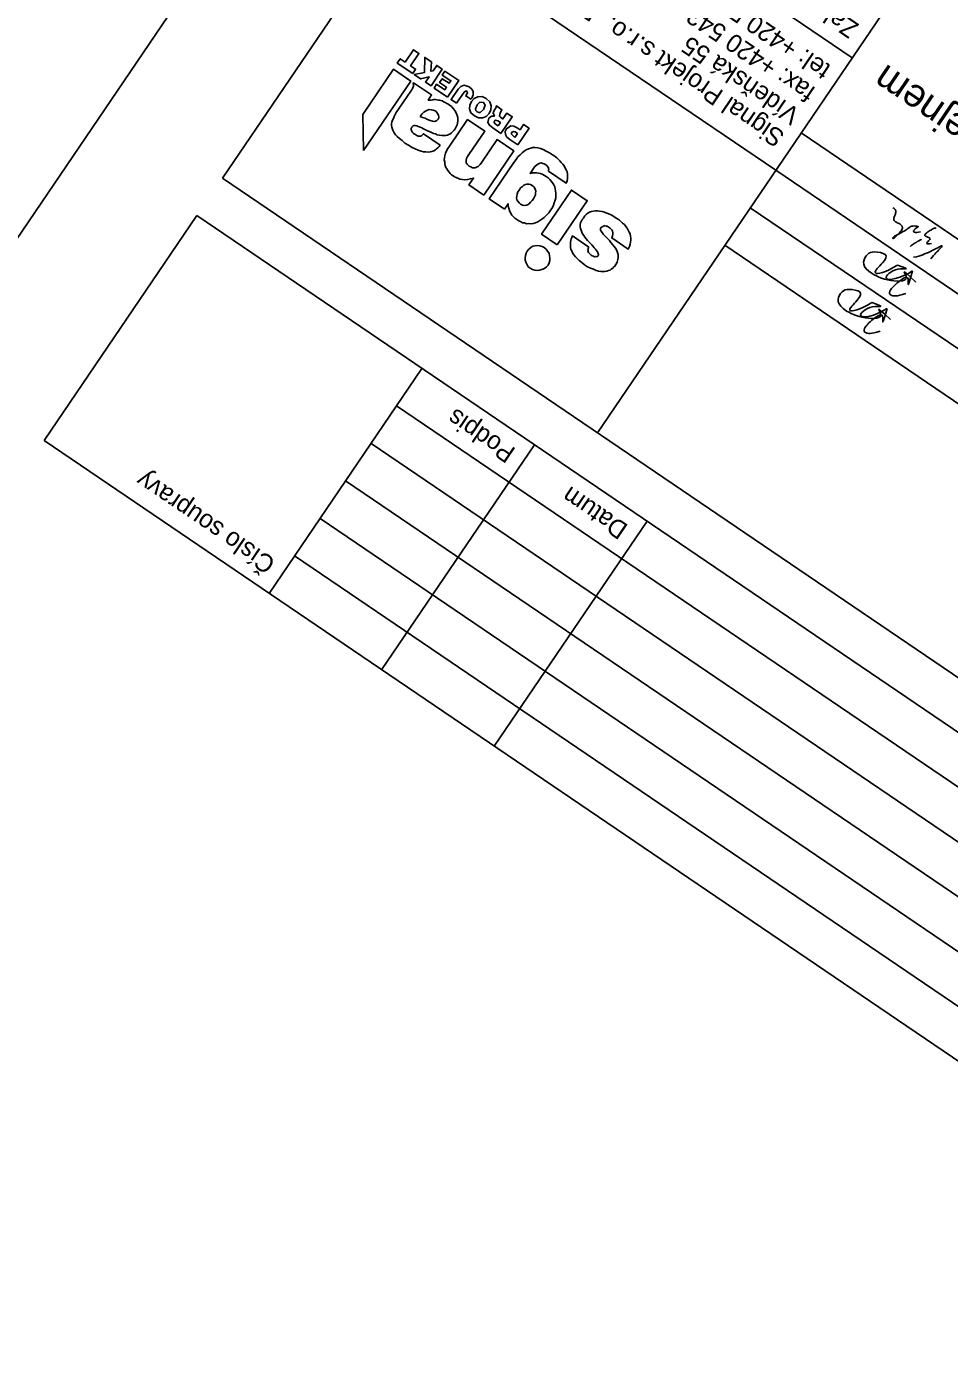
# Model space of a CAD drawing. Extents: x -621145 to -620110, y -1122807 to -1121971.
# Drawn here: x -621094.2 to -621043.4, y -1122204.9 to -1122131.1 of the extents above; entities that cross this region are included whole.
import ezdxf

# ---------------------------------------------------------------- set-up
doc = ezdxf.new("R2010")
doc.units = 0
for name, color, linetype in [('Default', 7, 'Continuous'), ('Info o rozpiskách', 7, 'Continuous'), ('LICHE', 7, 'Continuous'), ('Podpisy', 7, 'Continuous'), ('popis', 7, 'Continuous'), ('Ramečky', 7, 'Continuous'), ('RÁMY', 7, 'Continuous'), ('Text', 7, 'Continuous'), ('Text barevný', 7, 'Continuous')]:
    doc.layers.add(name, color=color, linetype=linetype)

# ---------------------------------------------------------------- blocks, each defined once
blk = doc.blocks.new('A$C65FD2E33_1')
at = {"layer": 'popis'}
for points in [[(-0.001696, 0.001402), (-0.001243, 0.00199), (-0.000783, 0.002198), (-0.00058, 0.001995), (-0.000655, 0.001241), (-0.001176, -0.000273), (-0.001696, 0.001402), (-0.001176, -0.000273)], [(0, 0), (0.000429, 0.000991), (0.001306, 0.001883), (0.000916, 0.000325), (0.00104, -0.00033), (0.00205, 0.000162), (0.002331, 0.000523), (0.002284, 0.001298), (0.001686, 0.001657), (0.000024, 0.001491), (-0.001834, 0.000276), (0, 0), (-0.001834, 0.000276)], [(-0.001176, -0.000273), (-0.00069, 0.000816), (0.000494, 0.001844), (0, 0), (-0.001176, -0.000273), (0, 0)]]:
    blk.add_open_spline(points, degree=3, dxfattribs=at)
blk = doc.blocks.new('podpis_vyvoda')
at = {"layer": 'Default'}
for points, degree in [([(0.027, 0.238), (0.019, 0.149), (-0.001, 0.052), (-0.009, -0.025), (0.03, 0.048), (0.089, 0.161), (0.154, 0.255), (0.197, 0.319), (0.239, 0.357)], 3), ([(0.289, 0.083), (0.328, 0.161), (0.348, 0.206), (0.366, 0.257)], 2), ([(0.361, 0.009), (0.395, 0.041), (0.415, 0.059), (0.44, 0.059), (0.446, 0.056), (0.449, 0.046), (0.448, 0.031), (0.447, 0.012), (0.439, -0.011), (0.429, -0.026), (0.425, -0.037), (0.431, -0.039), (0.466, -0.022), (0.498, 0), (0.518, 0.019), (0.527, 0.042), (0.531, 0.068), (0.542, 0.096), (0.556, 0.126), (0.582, 0.173), (0.6, 0.207), (0.62, 0.245), (0.63, 0.266), (0.634, 0.282), (0.636, 0.302), (0.629, 0.305), (0.62, 0.291), (0.614, 0.271), (0.61, 0.243), (0.596, 0.181), (0.594, 0.151), (0.596, 0.113), (0.605, 0.097), (0.62, 0.085), (0.645, 0.077), (0.675, 0.079), (0.701, 0.085), (0.734, 0.088), (0.757, 0.086), (0.775, 0.068), (0.783, 0.042), (0.788, 0.018), (0.795, -0.004), (0.804, -0.027), (0.816, -0.045), (0.832, -0.054), (0.848, -0.058), (0.874, -0.055)], 3), ([(0.141, 0.058), (0.176, 0.089), (0.196, 0.096), (0.203, 0.087), (0.195, 0.044), (0.19, 0.021), (0.197, 0.004), (0.217, 0.007), (0.27, 0.019), (0.283, 0.019), (0.288, 0.002), (0.28, -0.031), (0.269, -0.069), (0.243, -0.119), (0.227, -0.15), (0.219, -0.158), (0.203, -0.155)], 3)]:
    blk.add_open_spline(points, degree=degree, dxfattribs=at)

msp = doc.modelspace()

# ---------------------------------------------------------------- linework, layer by layer
at = {"layer": 'Info o rozpiskách'}
for points in [[(-621072.952, -1122133.722), (-621073.801, -1122133.146), (-621073.638, -1122132.906), (-621073.368, -1122133.09), (-621072.907, -1122132.411), (-621072.606, -1122132.615), (-621073.067, -1122133.294), (-621072.79, -1122133.483), (-621072.952, -1122133.722)], [(-621071.941, -1122134.409), (-621072.25, -1122134.199), (-621072.05, -1122133.906), (-621072.512, -1122134.021), (-621072.867, -1122133.78), (-621072.292, -1122133.663), (-621072.282, -1122132.835), (-621071.919, -1122133.082), (-621071.942, -1122133.596), (-621071.825, -1122133.574), (-621071.626, -1122133.281), (-621071.317, -1122133.49), (-621071.941, -1122134.409)], [(-621071.023, -1122135.033), (-621071.771, -1122134.524), (-621071.63, -1122134.316), (-621071.182, -1122134.62), (-621071.088, -1122134.481), (-621071.466, -1122134.224), (-621071.319, -1122134.008), (-621070.941, -1122134.265), (-621070.847, -1122134.126), (-621071.317, -1122133.806), (-621071.171, -1122133.59), (-621070.399, -1122134.114), (-621071.023, -1122135.033)], [(-621070.529, -1122135.368), (-621070.83, -1122135.164), (-621070.442, -1122134.592), (-621070.29, -1122134.436), (-621070.122, -1122134.37), (-621069.835, -1122134.463), (-621069.692, -1122134.583), (-621069.618, -1122134.724), (-621069.619, -1122134.892), (-621069.698, -1122135.075), (-621069.753, -1122135.139), (-621070.023, -1122134.956), (-621069.934, -1122134.791), (-621069.964, -1122134.703), (-621070.039, -1122134.697), (-621070.115, -1122134.758), (-621070.529, -1122135.368)], [(-621069.549, -1122136.067), (-621069.737, -1122135.894), (-621069.826, -1122135.676), (-621069.805, -1122135.464), (-621069.716, -1122135.266), (-621069.554, -1122135.094), (-621069.357, -1122135.003), (-621069.129, -1122134.999), (-621068.894, -1122135.102), (-621068.705, -1122135.288), (-621068.621, -1122135.513), (-621068.649, -1122135.72), (-621068.743, -1122135.926), (-621068.9, -1122136.091), (-621069.092, -1122136.174), (-621069.32, -1122136.177), (-621069.549, -1122136.067)], [(-621069.397, -1122135.843), (-621069.31, -1122135.88), (-621069.224, -1122135.871), (-621069.047, -1122135.709), (-621068.957, -1122135.477), (-621069.046, -1122135.326), (-621069.245, -1122135.304), (-621069.399, -1122135.447), (-621069.484, -1122135.672), (-621069.472, -1122135.77), (-621069.397, -1122135.843)], [(-621068.083, -1122137.029), (-621068.531, -1122136.725), (-621068.72, -1122136.573), (-621068.81, -1122136.423), (-621068.754, -1122136.19), (-621068.608, -1122136.075), (-621068.447, -1122136.071), (-621068.516, -1122135.889), (-621068.434, -1122135.719), (-621068.387, -1122135.65), (-621068.347, -1122135.575), (-621068.355, -1122135.536), (-621068.339, -1122135.513), (-621068.03, -1122135.723), (-621068.125, -1122135.896), (-621068.17, -1122136.079), (-621068.114, -1122136.129), (-621068.026, -1122136.199), (-621067.98, -1122136.23), (-621067.76, -1122135.906), (-621067.459, -1122136.111), (-621068.083, -1122137.029)], [(-621068.242, -1122136.616), (-621068.117, -1122136.431), (-621068.248, -1122136.342), (-621068.377, -1122136.299), (-621068.437, -1122136.338), (-621068.453, -1122136.428), (-621068.389, -1122136.517), (-621068.242, -1122136.616)], [(-621067.157, -1122137.658), (-621067.597, -1122137.359), (-621067.756, -1122137.228), (-621067.838, -1122137.083), (-621067.847, -1122136.93), (-621067.77, -1122136.768), (-621067.546, -1122136.604), (-621067.375, -1122136.619), (-621067.182, -1122136.716), (-621067.028, -1122136.821), (-621066.834, -1122136.535), (-621066.533, -1122136.74), (-621067.157, -1122137.658)], [(-621067.316, -1122137.245), (-621067.175, -1122137.037), (-621067.306, -1122136.948), (-621067.399, -1122136.918), (-621067.495, -1122136.977), (-621067.511, -1122137.068), (-621067.401, -1122137.188), (-621067.316, -1122137.245)], [(-621066.475, -1122144.458), (-621066.578, -1122144.377), (-621066.645, -1122144.276), (-621066.7, -1122144.159), (-621066.753, -1122144.021), (-621066.758, -1122143.894), (-621066.736, -1122143.762), (-621066.701, -1122143.628), (-621066.635, -1122143.515), (-621066.554, -1122143.412), (-621066.437, -1122143.323), (-621066.323, -1122143.254), (-621066.214, -1122143.226), (-621066.056, -1122143.209), (-621065.937, -1122143.234), (-621065.818, -1122143.258), (-621065.705, -1122143.324), (-621065.586, -1122143.415), (-621065.512, -1122143.522), (-621065.43, -1122143.634), (-621065.411, -1122143.771), (-621065.389, -1122143.888), (-621065.388, -1122144.035), (-621065.435, -1122144.172), (-621065.485, -1122144.296), (-621065.582, -1122144.388), (-621065.686, -1122144.475), (-621065.824, -1122144.528), (-621065.951, -1122144.566), (-621066.075, -1122144.583), (-621066.22, -1122144.564), (-621066.346, -1122144.534), (-621066.475, -1122144.458)]]:
    msp.add_lwpolyline(points, dxfattribs=at)
at = {"layer": 'popis'}
for points in [[(-621075.658, -1122137.973), (-621073.054, -1122134.138), (-621074.011, -1122133.488), (-621075.704, -1122135.981), (-621075.658, -1122137.973)], [(-621071.439, -1122137.671), (-621072.357, -1122137.047), (-621072.412, -1122137.111), (-621072.464, -1122137.154), (-621072.521, -1122137.172), (-621072.581, -1122137.177), (-621072.648, -1122137.176), (-621072.72, -1122137.15), (-621072.774, -1122137.113), (-621072.836, -1122137.071), (-621072.905, -1122137.024), (-621072.969, -1122136.969), (-621073.003, -1122136.902), (-621073.023, -1122136.865), (-621073.033, -1122136.813), (-621073.043, -1122136.761), (-621073.016, -1122136.723), (-621073.006, -1122136.674), (-621072.964, -1122136.646), (-621072.925, -1122136.605), (-621072.865, -1122136.6), (-621072.806, -1122136.596), (-621072.731, -1122136.601), (-621072.643, -1122136.638), (-621072.548, -1122136.68), (-621072.452, -1122136.723), (-621072.354, -1122136.778), (-621072.244, -1122136.83), (-621072.141, -1122136.878), (-621072.03, -1122136.931), (-621071.914, -1122136.975), (-621071.803, -1122137.028), (-621071.697, -1122137.055), (-621071.594, -1122137.103), (-621071.475, -1122137.127), (-621071.351, -1122137.144), (-621071.232, -1122137.134), (-621071.136, -1122137.143), (-621071.04, -1122137.118), (-621070.96, -1122137.082), (-621070.903, -1122137.064), (-621070.833, -1122137.011), (-621070.776, -1122136.959), (-621070.713, -1122136.9), (-621070.663, -1122136.844), (-621070.616, -1122136.774), (-621070.503, -1122136.558), (-621070.455, -1122136.354), (-621070.46, -1122136.147), (-621070.511, -1122135.989), (-621070.59, -1122135.823), (-621070.7, -1122135.669), (-621070.81, -1122135.549), (-621070.943, -1122135.447), (-621071.005, -1122135.405), (-621071.064, -1122135.376), (-621071.126, -1122135.334), (-621071.206, -1122135.303), (-621071.258, -1122135.279), (-621071.332, -1122135.239), (-621071.405, -1122135.213), (-621071.469, -1122135.192), (-621071.544, -1122135.186), (-621071.619, -1122135.18), (-621071.689, -1122135.166), (-621071.777, -1122135.163), (-621071.849, -1122135.17), (-621071.927, -1122135.185), (-621072.02, -1122135.189), (-621072.093, -1122135.197), (-621071.914, -1122134.901), (-621072.902, -1122134.23), (-621072.928, -1122134.268), (-621072.911, -1122134.359), (-621072.914, -1122134.413), (-621072.917, -1122134.468), (-621072.938, -1122134.499), (-621072.954, -1122134.555), (-621072.975, -1122134.586), (-621073.006, -1122134.632), (-621073.048, -1122134.694), (-621073.855, -1122135.883), (-621073.923, -1122135.983), (-621073.968, -1122136.099), (-621074.016, -1122136.202), (-621074.063, -1122136.305), (-621074.093, -1122136.398), (-621074.111, -1122136.475), (-621074.12, -1122136.571), (-621074.098, -1122136.688), (-621074.065, -1122136.789), (-621074.027, -1122136.882), (-621073.966, -1122136.992), (-621073.892, -1122137.099), (-621073.799, -1122137.195), (-621073.671, -1122137.305), (-621073.535, -1122137.42), (-621073.381, -1122137.558), (-621073.182, -1122137.681), (-621072.972, -1122137.802), (-621072.809, -1122137.879), (-621072.647, -1122137.955), (-621072.489, -1122138.006), (-621072.363, -1122138.035), (-621072.226, -1122138.049), (-621072.104, -1122138.053), (-621071.985, -1122138.044), (-621071.889, -1122138.019), (-621071.78, -1122137.991), (-621071.697, -1122137.935), (-621071.64, -1122137.884), (-621071.564, -1122137.822), (-621071.496, -1122137.755), (-621071.439, -1122137.671)], [(-621072.545, -1122136.096), (-621072.54, -1122136.088), (-621072.524, -1122136.065), (-621072.514, -1122136.05), (-621072.425, -1122135.952), (-621072.344, -1122135.849), (-621072.253, -1122135.798), (-621072.144, -1122135.737), (-621072.035, -1122135.709), (-621071.931, -1122135.723), (-621071.821, -1122135.742), (-621071.72, -1122135.777), (-621071.65, -1122135.824), (-621071.615, -1122135.871), (-621071.584, -1122135.925), (-621071.553, -1122135.98), (-621071.528, -1122136.042), (-621071.516, -1122136.107), (-621071.511, -1122136.167), (-621071.545, -1122136.233), (-621071.629, -1122136.324), (-621071.735, -1122136.364), (-621071.859, -1122136.347), (-621071.981, -1122136.31), (-621072.133, -1122136.252), (-621072.259, -1122136.189), (-621072.409, -1122136.143), (-621072.545, -1122136.096)], [(-621069.025, -1122140.426), (-621067.374, -1122137.995), (-621068.301, -1122137.366), (-621069.144, -1122138.608), (-621069.233, -1122138.74), (-621069.34, -1122138.847), (-621069.426, -1122138.891), (-621069.499, -1122138.932), (-621069.579, -1122138.933), (-621069.662, -1122138.922), (-621069.744, -1122138.878), (-621069.832, -1122138.841), (-621069.899, -1122138.773), (-621069.942, -1122138.721), (-621069.996, -1122138.65), (-621070.003, -1122138.578), (-621069.997, -1122138.503), (-621069.981, -1122138.412), (-621069.923, -1122138.294), (-621069.85, -1122138.186), (-621068.98, -1122136.905), (-621069.921, -1122136.265), (-621070.917, -1122137.732), (-621071.006, -1122137.863), (-621071.082, -1122137.992), (-621071.137, -1122138.123), (-621071.172, -1122138.257), (-621071.197, -1122138.376), (-621071.208, -1122138.493), (-621071.186, -1122138.609), (-621071.187, -1122138.71), (-621071.161, -1122138.806), (-621071.129, -1122138.907), (-621071.067, -1122138.983), (-621071.016, -1122139.074), (-621070.945, -1122139.167), (-621070.878, -1122139.235), (-621070.811, -1122139.303), (-621070.719, -1122139.366), (-621070.603, -1122139.445), (-621070.466, -1122139.492), (-621070.355, -1122139.545), (-621070.211, -1122139.564), (-621070.074, -1122139.579), (-621069.921, -1122139.57), (-621069.768, -1122139.527), (-621069.594, -1122139.487), (-621069.851, -1122139.865), (-621069.025, -1122140.426)], [(-621067.896, -1122141.204), (-621067.692, -1122140.903), (-621067.68, -1122141.035), (-621067.65, -1122141.157), (-621067.612, -1122141.284), (-621067.554, -1122141.414), (-621067.485, -1122141.528), (-621067.408, -1122141.614), (-621067.318, -1122141.698), (-621067.208, -1122141.784), (-621067.095, -1122141.85), (-621067.012, -1122141.895), (-621066.893, -1122141.952), (-621066.79, -1122141.966), (-621066.682, -1122142.006), (-621066.555, -1122142.002), (-621066.431, -1122142.018), (-621066.301, -1122141.994), (-621066.187, -1122141.959), (-621066.057, -1122141.9), (-621065.935, -1122141.837), (-621065.828, -1122141.762), (-621065.693, -1122141.663), (-621065.568, -1122141.545), (-621065.448, -1122141.401), (-621065.338, -1122141.239), (-621065.248, -1122141.108), (-621065.185, -1122140.981), (-621065.143, -1122140.852), (-621065.095, -1122140.716), (-621065.066, -1122140.589), (-621065.051, -1122140.452), (-621065.063, -1122140.32), (-621065.073, -1122140.201), (-621065.095, -1122140.084), (-621065.123, -1122139.975), (-621065.178, -1122139.859), (-621065.245, -1122139.757), (-621065.311, -1122139.656), (-621065.396, -1122139.564), (-621065.486, -1122139.481), (-621065.594, -1122139.407), (-621065.686, -1122139.345), (-621065.782, -1122139.302), (-621065.9, -1122139.244), (-621066.019, -1122139.22), (-621066.13, -1122139.201), (-621066.251, -1122139.197), (-621066.35, -1122139.209), (-621066.472, -1122139.239), (-621066.32, -1122139.016), (-621066.21, -1122138.854), (-621066.105, -1122138.767), (-621066.009, -1122138.708), (-621065.936, -1122138.667), (-621065.851, -1122138.657), (-621065.779, -1122138.684), (-621065.694, -1122138.708), (-621065.617, -1122138.76), (-621065.578, -1122138.787), (-621065.529, -1122138.831), (-621065.493, -1122138.878), (-621065.465, -1122138.92), (-621065.463, -1122138.966), (-621065.445, -1122139.023), (-621065.459, -1122139.059), (-621065.47, -1122139.108), (-621064.49, -1122139.774), (-621064.429, -1122139.635), (-621064.417, -1122139.519), (-621064.408, -1122139.389), (-621064.415, -1122139.283), (-621064.427, -1122139.151), (-621064.488, -1122139.042), (-621064.547, -1122138.946), (-621064.605, -1122138.816), (-621064.677, -1122138.722), (-621064.762, -1122138.631), (-621064.839, -1122138.545), (-621064.931, -1122138.448), (-621065.01, -1122138.383), (-621065.082, -1122138.323), (-621065.17, -1122138.252), (-621065.239, -1122138.205), (-621065.414, -1122138.097), (-621065.587, -1122138.003), (-621065.757, -1122137.921), (-621065.901, -1122137.868), (-621066.051, -1122137.823), (-621066.195, -1122137.803), (-621066.323, -1122137.807), (-621066.444, -1122137.838), (-621066.571, -1122137.875), (-621066.688, -1122137.931), (-621066.802, -1122138), (-621066.92, -1122138.09), (-621067.019, -1122138.202), (-621067.152, -1122138.315), (-621067.251, -1122138.462), (-621067.367, -1122138.631), (-621068.729, -1122140.638), (-621067.896, -1122141.204)], [(-621067.009, -1122140.927), (-621067.083, -1122140.854), (-621067.153, -1122140.773), (-621067.204, -1122140.682), (-621067.228, -1122140.586), (-621067.215, -1122140.483), (-621067.188, -1122140.377), (-621067.145, -1122140.248), (-621067.067, -1122140.132), (-621066.999, -1122140.032), (-621066.905, -1122139.96), (-621066.819, -1122139.883), (-621066.733, -1122139.84), (-621066.655, -1122139.825), (-621066.549, -1122139.818), (-621066.464, -1122139.842), (-621066.366, -1122139.898), (-621066.279, -1122139.968), (-621066.217, -1122140.044), (-621066.177, -1122140.15), (-621066.157, -1122140.22), (-621066.171, -1122140.323), (-621066.179, -1122140.419), (-621066.227, -1122140.522), (-621066.287, -1122140.628), (-621066.368, -1122140.731), (-621066.452, -1122140.82), (-621066.53, -1122140.903), (-621066.618, -1122140.967), (-621066.694, -1122140.994), (-621066.805, -1122141.009), (-621066.898, -1122140.98), (-621067.009, -1122140.927)], [(-621064.982, -1122143.172), (-621063.331, -1122140.741), (-621064.195, -1122140.154), (-621065.846, -1122142.585), (-621064.982, -1122143.172)], [(-621063.239, -1122143.296), (-621064.149, -1122142.677), (-621064.179, -1122142.77), (-621064.21, -1122142.85), (-621064.234, -1122142.935), (-621064.251, -1122143.026), (-621064.254, -1122143.114), (-621064.255, -1122143.214), (-621064.251, -1122143.307), (-621064.228, -1122143.424), (-621064.185, -1122143.51), (-621064.132, -1122143.614), (-621064.065, -1122143.716), (-621063.983, -1122143.828), (-621063.883, -1122143.929), (-621063.768, -1122144.041), (-621063.632, -1122144.156), (-621063.475, -1122144.274), (-621063.308, -1122144.377), (-621063.143, -1122144.466), (-621062.991, -1122144.524), (-621062.844, -1122144.59), (-621062.709, -1122144.625), (-621062.585, -1122144.642), (-621062.472, -1122144.64), (-621062.358, -1122144.638), (-621062.246, -1122144.624), (-621062.158, -1122144.593), (-621062.07, -1122144.563), (-621062, -1122144.51), (-621061.916, -1122144.453), (-621061.854, -1122144.394), (-621061.802, -1122144.351), (-621061.744, -1122144.266), (-621061.683, -1122144.127), (-621061.638, -1122143.977), (-621061.614, -1122143.858), (-621061.623, -1122143.705), (-621061.655, -1122143.604), (-621061.693, -1122143.477), (-621061.762, -1122143.363), (-621061.849, -1122143.258), (-621061.931, -1122143.146), (-621062.018, -1122143.042), (-621062.105, -1122142.938), (-621062.192, -1122142.834), (-621062.29, -1122142.745), (-621062.372, -1122142.667), (-621062.449, -1122142.58), (-621062.507, -1122142.484), (-621062.571, -1122142.396), (-621062.589, -1122142.339), (-621062.594, -1122142.279), (-621062.575, -1122142.235), (-621062.512, -1122142.176), (-621062.468, -1122142.161), (-621062.427, -1122142.133), (-621062.36, -1122142.134), (-621062.285, -1122142.139), (-621062.236, -1122142.15), (-621062.171, -1122142.172), (-621062.117, -1122142.208), (-621062.063, -1122142.245), (-621062.012, -1122142.302), (-621061.958, -1122142.373), (-621061.935, -1122142.422), (-621061.918, -1122142.513), (-621061.91, -1122142.585), (-621061.932, -1122142.683), (-621061.972, -1122142.792), (-621061.069, -1122143.405), (-621061.001, -1122143.271), (-621060.958, -1122143.142), (-621060.934, -1122143.023), (-621060.928, -1122142.915), (-621060.929, -1122142.801), (-621060.944, -1122142.689), (-621060.966, -1122142.573), (-621061.007, -1122142.466), (-621061.068, -1122142.357), (-621061.129, -1122142.248), (-621061.201, -1122142.154), (-621061.28, -1122142.055), (-621061.391, -1122141.969), (-621061.475, -1122141.877), (-621061.57, -1122141.802), (-621061.701, -1122141.712), (-621061.838, -1122141.631), (-621061.969, -1122141.542), (-621062.108, -1122141.481), (-621062.247, -1122141.421), (-621062.379, -1122141.365), (-621062.505, -1122141.336), (-621062.642, -1122141.321), (-621062.754, -1122141.303), (-621062.875, -1122141.299), (-621062.999, -1122141.316), (-621063.095, -1122141.341), (-621063.196, -1122141.374), (-621063.295, -1122141.419), (-621063.389, -1122141.491), (-621063.46, -1122141.578), (-621063.523, -1122141.671), (-621063.538, -1122141.694), (-621063.554, -1122141.717), (-621063.57, -1122141.74), (-621063.586, -1122141.764), (-621063.606, -1122141.794), (-621063.622, -1122141.818), (-621063.633, -1122141.833), (-621063.643, -1122141.848), (-621063.703, -1122141.954), (-621063.717, -1122142.057), (-621063.716, -1122142.171), (-621063.691, -1122142.267), (-621063.666, -1122142.363), (-621063.63, -1122142.477), (-621063.587, -1122142.563), (-621063.515, -1122142.657), (-621063.451, -1122142.745), (-621063.38, -1122142.839), (-621063.308, -1122142.933), (-621063.234, -1122143.006), (-621063.149, -1122143.097), (-621063.08, -1122143.178), (-621062.998, -1122143.257), (-621062.936, -1122143.332), (-621062.88, -1122143.415), (-621062.821, -1122143.478), (-621062.788, -1122143.545), (-621062.745, -1122143.597), (-621062.73, -1122143.642), (-621062.704, -1122143.704), (-621062.705, -1122143.738), (-621062.725, -1122143.768), (-621062.746, -1122143.799), (-621062.783, -1122143.82), (-621062.834, -1122143.829), (-621062.876, -1122143.824), (-621062.928, -1122143.834), (-621062.982, -1122143.797), (-621063.054, -1122143.771), (-621063.108, -1122143.734), (-621063.17, -1122143.692), (-621063.213, -1122143.64), (-621063.254, -1122143.601), (-621063.285, -1122143.546), (-621063.29, -1122143.487), (-621063.279, -1122143.438), (-621063.278, -1122143.37), (-621063.239, -1122143.296)]]:
    msp.add_lwpolyline(points, dxfattribs=at)
at = {"layer": 'Ramečky'}
for p, q in [((-621059.567, -1122104.336), (-621083.445, -1122139.495)), ((-621048.718, -1122132.859), (-621069.399, -1122118.813)), ((-621038.886, -1122118.382), (-621062.763, -1122153.54)), ((-620997.755, -1122173.513), (-621051.527, -1122136.995)), ((-621083.445, -1122139.495), (-621008.991, -1122190.059)), ((-620999.16, -1122175.582), (-621052.931, -1122139.063)), ((-621000.564, -1122177.65), (-621054.336, -1122141.131)), ((-621093.277, -1122153.972), (-621084.849, -1122141.563)), ((-621084.849, -1122141.563), (-621010.396, -1122192.127)), ((-621001.969, -1122179.718), (-621055.741, -1122143.199)), ((-621080.868, -1122162.399), (-621072.44, -1122149.99)), ((-621073.845, -1122152.058), (-621011.801, -1122194.195)), ((-621093.277, -1122153.972), (-621018.823, -1122204.536)), ((-621075.25, -1122154.126), (-621013.205, -1122196.263)), ((-621074.663, -1122166.613), (-621066.236, -1122154.204)), ((-621076.654, -1122156.195), (-621014.61, -1122198.331)), ((-621078.059, -1122158.263), (-621016.014, -1122200.399)), ((-621068.459, -1122170.826), (-621060.032, -1122158.417)), ((-621079.463, -1122160.331), (-621017.419, -1122202.467))]:
    msp.add_line(p, q, dxfattribs=at)
msp.add_lwpolyline([(-621052.931, -1122139.063), (-621073.613, -1122125.018)], dxfattribs=at)
at = {"layer": 'RÁMY'}
msp.add_lwpolyline([(-621061.558, -1122093.918), (-620192.937, -1122683.831), (-620276.367, -1122806.679), (-621144.989, -1122216.766)], close=True, dxfattribs=at)

# ---------------------------------------------------------------- block references
at = {"layer": 'LICHE', "xscale": 3.918060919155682, "yscale": 3.9180609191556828, "rotation": 145.81810353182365}
msp.add_blockref('podpis_vyvoda', (-621043.768, -1122143.229), dxfattribs=at)
at = {"layer": 'Podpisy', "xscale": 744.8335616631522, "yscale": 744.8335616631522, "rotation": 145.81811799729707}
for p in [(-621046.223, -1122144.286), (-621047.628, -1122146.354)]:
    msp.add_blockref('A$C65FD2E33_1', p, dxfattribs=at)

# ---------------------------------------------------------------- texts
at = {"layer": 'Text'}
for s, p in [('Zak. číslo zhotov.', (-621048.293, -1122131.032)), ('tel: +420 543 233 962', (-621049.83, -1122133.312)), ('fax: +420 543 331 046', (-621050.673, -1122134.553)), ('Signal Projekt s.r.o., Brno', (-621052.366, -1122137.03)), ('Vídeňská 55', (-621051.523, -1122135.789)), ('Podpis', (-621067.216, -1122154.445)), ('Číslo soupravy', (-621080.443, -1122160.572)), ('Datum', (-621061.011, -1122158.659))]:
    msp.add_text(s, height=1, rotation=145.81812, dxfattribs=at).set_placement(p)
at = {"layer": 'Text barevný'}
msp.add_text('Oprava zabezpečovacího zařízení v ŽST Bystřice nad Pernštejnem', height=1.55893, rotation=145.81812, dxfattribs=at).set_placement((-620995.487, -1122168.05))

doc.saveas('drawing.dxf')
